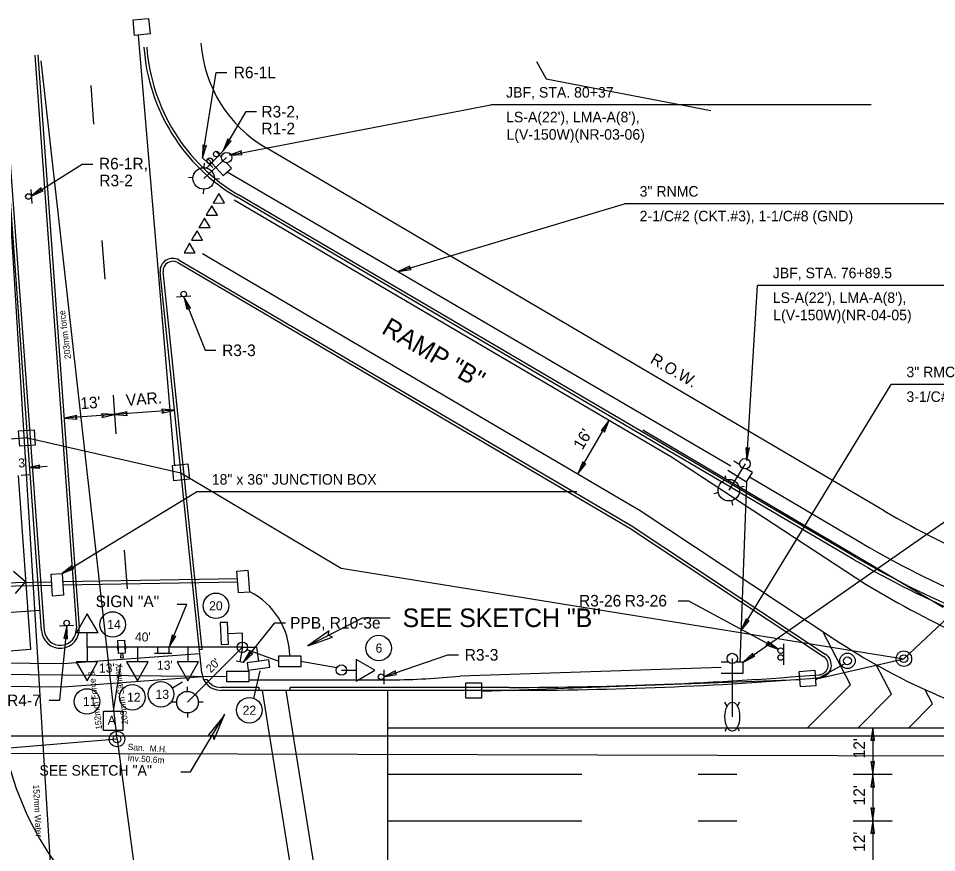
# Model space of a CAD drawing. Extents: x 488740 to 507913, y 466518 to 497949.
# Drawn here: x 503498.8 to 503735.9, y 496091.2 to 496306.6 of the extents above; entities that cross this region are included whole.
import ezdxf

# ---------------------------------------------------------------- set-up
doc = ezdxf.new("R2010")
doc.units = 0
for name, color, linetype in [('1', 7, 'Continuous'), ('11', 7, 'Continuous'), ('23', 7, 'Continuous'), ('31', 7, 'Continuous'), ('36', 7, 'Continuous'), ('38', 7, 'Continuous'), ('41', 7, 'Continuous'), ('5', 7, 'Continuous'), ('7', 7, 'Continuous'), ('9', 7, 'Continuous')]:
    doc.layers.add(name, color=color, linetype=linetype)

msp = doc.modelspace()

# ---------------------------------------------------------------- linework, layer by layer
at = {"layer": '1'}
for p, q in [((503504.8, 496148.54), (503494.11, 496296.42)), ((503505.55, 496148.6), (503494.86, 496296.48)), ((503503.13, 496297.07), (503513.82, 496149.2)), ((503503.88, 496297.13), (503514.57, 496149.25)), ((503722.34, 496179.43), (503562.78, 496273.13)), ((503714.59, 496166.85), (503555.3, 496260.39)), ((503714.97, 496167.5), (503555.68, 496261.04)), ((503539.97, 496243.53), (503656.64, 496175.01)), ((503540.35, 496244.17), (503657.04, 496175.65)), ((503546.19, 496137.67), (503535.44, 496241.12)), ((503546.32, 496143.64), (503536.18, 496241.2)), ((503656.64, 496175.01), (503706.67, 496141.85)), ((503657.04, 496175.65), (503707.08, 496142.47)), ((503546.32, 496143.64), (503545.57, 496143.56)), ((503547.52, 496135.89), (503546.71, 496135.8)), ((503560.96, 496133.88), (503551.07, 496133.88)), ((503560.96, 496133.08), (503560.96, 496133.88)), ((503568.97, 496133.08), (503568.97, 496133.88)), ((503625.63, 496133.88), (503568.97, 496133.88)), ((503625.63, 496133.12), (503551.07, 496133.12))]:
    msp.add_line(p, q, dxfattribs=at)
for points in [[(503528.44, 496306.17), (503532.42, 496306.58), (503532.84, 496302.6), (503528.86, 496302.19)], [(503498.92, 496200.1), (503502.92, 496200.39), (503503.2, 496196.4), (503499.21, 496196.11)], [(503538.6, 496191.16), (503542.58, 496191.57), (503542.99, 496187.59), (503539.01, 496187.18)], [(503700.73, 496134.02), (503700.43, 496138.01), (503704.42, 496138.32), (503704.73, 496134.32)], [(503614.38, 496131.07), (503614.38, 496135.07), (503618.38, 496135.07), (503618.38, 496131.07)]]:
    msp.add_lwpolyline(points, close=True, dxfattribs=at)
for centre, radius in [((503727.42, 496141.28), 2), ((503712.86, 496140.74), 2), ((503712.86, 496140.74), 0.999), ((503727.42, 496141.28), 0.999)]:
    msp.add_circle(centre, radius, dxfattribs=at)
for centre, radius, start, end in [((503580.11, 496302.64), 34.22, 184.1335, 239.5771), ((503580.11, 496302.64), 48.99, 184.1335, 239.577), ((503580.11, 496302.64), 48.24, 184.1335, 239.577), ((503538.69, 496241.36), 3.27, 59.577, 184.1335), ((503538.69, 496241.36), 2.51, 59.577, 184.1335), ((503838.63, 496378.08), 230.18, 239.6562, 254.7212), ((503838.63, 496378.08), 244.21, 239.577, 254.7212), ((503838.63, 496378.08), 244.96, 239.577, 254.7212), ((503509.68, 496148.9), 4.9, 184.1335, 4.1335), ((503509.68, 496148.9), 4.15, 184.1335, 4.1335), ((503705.4, 496139.68), 2.51, 274.6874, 59.577), ((503705.43, 496139.66), 3.27, 274.6874, 59.577), ((503551.07, 496138.02), 4.9, 184.1335, 270), ((503625.63, 497112.95), 979.07, 270.00005, 274.68735), ((503625.63, 497112.95), 979.83, 270.00005, 274.68735), ((503551.07, 496138.02), 4.15, 210.9627, 270)]:
    msp.add_arc(centre, radius, start, end, dxfattribs=at)
at = {"layer": '11'}
for p, q in [((503553.31, 496271.28), (503620.8, 496284.24)), ((503718.98, 496284.24), (503620.8, 496284.24)), ((503596.89, 496241.24), (503655.28, 496258.68)), ((503753.47, 496258.68), (503655.28, 496258.68)), ((503686.92, 496192.41), (503689.65, 496237.62)), ((503787.84, 496237.62), (503689.65, 496237.62)), ((503685.37, 496148.52), (503724.14, 496212.06)), ((503822.32, 496212.06), (503724.14, 496212.06)), ((503685.96, 496140.4), (503758.51, 496190.99)), ((503543.3, 496112.11), (503552.14, 496126.95)), ((503540.82, 496112.11), (503543.3, 496112.11))]:
    msp.add_line(p, q, dxfattribs=at)
for points in [[(503553.31, 496271.28), (503556.65, 496271.44), (503556.21, 496271.84), (503556.47, 496272.37)], [(503596.89, 496241.24), (503600.2, 496241.73), (503599.72, 496242.08), (503599.93, 496242.64)], [(503686.92, 496192.41), (503687.59, 496195.69), (503687.1, 496195.36), (503686.65, 496195.74)], [(503685.37, 496148.52), (503687.49, 496151.1), (503686.91, 496151.04), (503686.69, 496151.59)], [(503685.96, 496140.4), (503688.94, 496141.91), (503688.38, 496142.09), (503688.4, 496142.68)], [(503551.97, 496126.6), (503547.77, 496121.4), (503548.95, 496121.53), (503549.4, 496120.43)]]:
    msp.add_lwpolyline(points, close=True, dxfattribs=at)
at = {"layer": '23'}
for p, q in [((503539.25, 496191.18), (503529.88, 496302.17)), ((503524.39, 495809.94), (503494.31, 496296.44)), ((503524.31, 496120.55), (503504.75, 496295.61)), ((503632.55, 496295.45), (503635.11, 496291.01)), ((503635.11, 496291.01), (503677.55, 496282.8)), ((503660.06, 496200.34), (503737.56, 496154.62)), ((503501.21, 496198.3), (503462.11, 496195.47)), ((503501.21, 496198.3), (503540.8, 496189.26)), ((503540.76, 496189.27), (503582.14, 496164.63)), ((503582.14, 496164.63), (503727.42, 496141.28)), ((503727.42, 496141.28), (503738.89, 496152.04)), ((503704.86, 496136.06), (503727.42, 496141.28)), ((503704.62, 496135.86), (503712.36, 496140.14)), ((503618.76, 496132.9), (503700.59, 496135.96)), ((503524.31, 496120.55), (503402.79, 496110.21)), ((503524.31, 496120.55), (503546.14, 495959.54)), ((503398.08, 496117.2), (503762.28, 496116.11))]:
    msp.add_line(p, q, dxfattribs=at)
for radius in [2, 0.999]:
    msp.add_circle((503524.31, 496120.55), radius, dxfattribs=at)
at = {"layer": '31'}
for p, q in [((503501.75, 496190.65), (503506.31, 496190.98)), ((503498.76, 496188.54), (503502.01, 496143.63)), ((503501.53, 496188.74), (503499.55, 496188.59)), ((503537.77, 496144.23), (503542.32, 496155.34)), ((503539.84, 496155.34), (503542.32, 496155.34)), ((503516.59, 496144.23), (503516.59, 496148.01)), ((503556.66, 496147.89), (503553, 496147.72)), ((503556.66, 496144.23), (503556.66, 496147.89)), ((503502.01, 496143.63), (503484.03, 496142.33)), ((503556.66, 496144.23), (503516.59, 496144.23)), ((503516.59, 496144.23), (503516.59, 496140.45)), ((503529.61, 496144.23), (503529.61, 496140.45)), ((503534.82, 496142.69), (503534.82, 496144.23)), ((503537.77, 496142.69), (503537.77, 496144.23)), ((503542.63, 496144.23), (503542.63, 496140.45)), ((503556.66, 496144.23), (503555.98, 496140.51)), ((503556.66, 496144.23), (503560.32, 496144.23)), ((503560.32, 496144.23), (503560.83, 496140.6)), ((503533.99, 496142.69), (503538.48, 496142.69)), ((503556.91, 496140.34), (503555.05, 496140.68)), ((503559.63, 496131.04), (503561.24, 496138.12)), ((503582.22, 496138.35), (503586, 496138.35)), ((503538.59, 496133.77), (503541.23, 496135.34))]:
    msp.add_line(p, q, dxfattribs=at)
for points in [[(503501.75, 496190.65), (503504.42, 496190.46), (503504.11, 496190.82), (503504.37, 496191.22)], [(503516.59, 496152.85), (503513.87, 496148.01), (503516.59, 496148.01), (503519.43, 496148.01)], [(503550.97, 496150.59), (503551.23, 496144.92), (503553.12, 496145.01), (503552.86, 496150.67)], [(503537.77, 496144.23), (503539.46, 496147.11), (503538.89, 496146.96), (503538.58, 496147.47)], [(503558.18, 496138.32), (503563.79, 496139.12), (503563.52, 496140.99), (503557.91, 496140.19)], [(503590.84, 496138.35), (503586, 496141.07), (503586, 496138.35), (503586, 496135.52)], [(503516.59, 496135.61), (503519.31, 496140.45), (503516.59, 496140.45), (503513.76, 496140.45)], [(503529.61, 496135.61), (503532.33, 496140.45), (503529.61, 496140.45), (503526.78, 496140.45)], [(503542.63, 496135.61), (503545.35, 496140.45), (503542.63, 496140.45), (503539.8, 496140.45)]]:
    msp.add_lwpolyline(points, close=True, dxfattribs=at)
for centre, radius in [((503552.61, 496270.66), 1.34), ((503686.41, 496191.63), 1.34), ((503549.84, 496154.94), 3.29), ((503523.19, 496150.12), 3.29), ((503591.86, 496144.03), 3.29), ((503556.66, 496144.23), 1.34), ((503683.12, 496141.35), 1.34), ((503582.22, 496138.35), 1.34), ((503528.27, 496131.33), 3.29), ((503535.66, 496132.1), 3.29), ((503516.55, 496130.25), 3.29), ((503558.46, 496127.97), 3.29)]:
    msp.add_circle(centre, radius, dxfattribs=at)
at = {"layer": '36'}
for p, q in [((503517.51, 496289.22), (503518.23, 496279.23)), ((503554.52, 496259.71), (503667.46, 496193.39)), ((503520.4, 496249.26), (503521.12, 496239.27)), ((503546.4, 496245.89), (503659.34, 496179.57)), ((503523.28, 496209.3), (503524.01, 496199.31)), ((503667.46, 496193.39), (503717.71, 496160.47)), ((503659.34, 496179.57), (503709.59, 496146.26)), ((503526.17, 496169.34), (503526.89, 496159.35)), ((503497.59, 496163.89), (503500.67, 496161.22)), ((503500.67, 496161.22), (503498, 496158.13)), ((503457, 496150.43), (503504.41, 496153.85)), ((503713.65, 496134.55), (503706.49, 496148.31)), ((503510.32, 496140.01), (503545.67, 496142.65)), ((503447.68, 496140.72), (503510.32, 496140.01)), ((503724.24, 496132.09), (503720.29, 496139.69)), ((503510.51, 496134), (503546.36, 496136.68)), ((503435.97, 496134.84), (503510.51, 496134)), ((503702.57, 496123.48), (503713.65, 496134.55)), ((503581.59, 496010.27), (503561.88, 496133.12)), ((503587.77, 496009.65), (503567.97, 496133.08)), ((503594.18, 496071.42), (503594.17, 496133.12)), ((503715.63, 496123.48), (503724.24, 496132.09)), ((503734.84, 496129.63), (503732.93, 496133.29)), ((503728.69, 496123.48), (503734.84, 496129.63)), ((503594.17, 496123.48), (503761.31, 496123.48)), ((503594.17, 496111.46), (503644.25, 496111.46)), ((503674.3, 496111.46), (503684.32, 496111.46)), ((503714.37, 496111.46), (503724.38, 496111.46)), ((503594.17, 496099.44), (503644.25, 496099.44)), ((503674.3, 496099.44), (503684.32, 496099.44)), ((503714.37, 496099.44), (503724.38, 496099.44))]:
    msp.add_line(p, q, dxfattribs=at)
for points in [[(503552.08, 496258.98), (503550.6, 496261.35), (503549.88, 496260.13), (503549.16, 496258.91)], [(503550.22, 496255.82), (503548.74, 496258.2), (503548.02, 496256.97), (503547.31, 496255.75)], [(503548.31, 496252.56), (503546.89, 496255.04), (503546.17, 496253.82), (503545.45, 496252.59)], [(503546.4, 496249.3), (503544.97, 496251.78), (503544.26, 496250.56), (503543.54, 496249.34)], [(503544.48, 496246.04), (503543.06, 496248.52), (503542.34, 496247.3), (503541.62, 496246.08)]]:
    msp.add_lwpolyline(points, close=True, dxfattribs=at)
for centre, radius, start, end in [((503851.62, 496381.27), 258.23, 238.7636, 252.127), ((503800.29, 496282.06), 163.3, 236.2647, 256.1902), ((503575.88, 496135.92), 82.51, 189.6092, 269.9061)]:
    msp.add_arc(centre, radius, start, end, dxfattribs=at)
at = {"layer": '38'}
for p, q in [((503539.15, 496205.42), (503523.65, 496204.3)), ((503523.65, 496204.3), (503510.66, 496203.37)), ((503643.26, 496189.01), (503651.37, 496202.83)), ((503719.37, 496123.48), (503719.37, 496111.46)), ((503719.37, 496111.46), (503719.37, 496099.44)), ((503719.37, 496099.44), (503719.37, 496087.42))]:
    msp.add_line(p, q, dxfattribs=at)
for points in [[(503523.65, 496204.3), (503526.98, 496204.07), (503526.59, 496204.52), (503526.91, 496205.01)], [(503539.15, 496205.42), (503535.81, 496205.66), (503536.2, 496205.21), (503535.88, 496204.71)], [(503510.66, 496203.37), (503513.99, 496203.13), (503513.6, 496203.58), (503513.92, 496204.08)], [(503523.65, 496204.3), (503520.31, 496204.54), (503520.7, 496204.09), (503520.38, 496203.59)], [(503651.37, 496202.83), (503649.29, 496200.22), (503649.88, 496200.29), (503650.11, 496199.74)], [(503643.26, 496189.01), (503645.34, 496191.63), (503644.75, 496191.56), (503644.52, 496192.11)], [(503719.37, 496123.48), (503718.9, 496120.17), (503719.37, 496120.53), (503719.85, 496120.17)], [(503719.37, 496111.46), (503719.85, 496114.77), (503719.37, 496114.41), (503718.9, 496114.77)], [(503719.37, 496111.46), (503718.9, 496108.15), (503719.37, 496108.51), (503719.85, 496108.15)], [(503719.37, 496099.44), (503719.85, 496102.75), (503719.37, 496102.39), (503718.9, 496102.75)], [(503719.37, 496099.44), (503718.9, 496096.13), (503719.37, 496096.49), (503719.85, 496096.13)]]:
    msp.add_lwpolyline(points, close=True, dxfattribs=at)
at = {"layer": '41'}
for p, q in [((503546.4, 496270.6), (503549.94, 496292.63)), ((503549.94, 496292.63), (503552.65, 496292.63)), ((503551.68, 496272.36), (503557.62, 496282.51)), ((503557.62, 496282.51), (503560.33, 496282.51)), ((503551.68, 496272.36), (503549.16, 496269.71)), ((503502.16, 496260.66), (503515.33, 496268.95)), ((503515.33, 496268.95), (503518.04, 496268.95)), ((503549.06, 496268.08), (503546.4, 496270.6)), ((503550, 496270.61), (503547.48, 496267.96)), ((503502.02, 496262.43), (503502.28, 496258.77)), ((503543.35, 496234.84), (503539.69, 496234.58)), ((503541.58, 496234.7), (503547.1, 496220.9)), ((503547.1, 496220.9), (503549.81, 496220.9)), ((503669.13, 496156.25), (503671.84, 496156.25)), ((503671.84, 496156.25), (503694.95, 496143.71)), ((503556.91, 496140.34), (503565.06, 496150.57)), ((503565.06, 496150.57), (503567.77, 496150.57)), ((503513.11, 496149.84), (503509.45, 496149.7)), ((503511.34, 496149.76), (503509.48, 496130.54)), ((503696.32, 496145.13), (503696.32, 496141.47)), ((503696.33, 496143.36), (503696.33, 496139.7)), ((503593.2, 496136.62), (503609.74, 496142.29)), ((503609.74, 496142.29), (503612.45, 496142.29)), ((503593.19, 496138.39), (503593.19, 496134.73)), ((503506.77, 496130.54), (503509.48, 496130.54))]:
    msp.add_line(p, q, dxfattribs=at)
for points in [[(503546.4, 496270.6), (503547.39, 496273.79), (503546.87, 496273.52), (503546.46, 496273.94)], [(503551.68, 496272.36), (503553.76, 496274.98), (503553.17, 496274.91), (503552.94, 496275.46)], [(503502.16, 496260.66), (503505.21, 496262.02), (503504.66, 496262.23), (503504.71, 496262.82)], [(503541.58, 496234.7), (503542.37, 496231.45), (503542.68, 496231.96), (503543.25, 496231.81)], [(503511.34, 496149.76), (503510.55, 496146.51), (503511.05, 496146.82), (503511.49, 496146.42)], [(503694.95, 496143.71), (503692.27, 496145.7), (503692.35, 496145.12), (503691.82, 496144.87)], [(503556.91, 496140.34), (503559.34, 496142.63), (503558.75, 496142.65), (503558.6, 496143.22)], [(503593.2, 496136.62), (503596.48, 496137.24), (503595.99, 496137.57), (503596.17, 496138.14)]]:
    msp.add_lwpolyline(points, close=True, dxfattribs=at)
for centre in [(503549.94, 496271.56), (503548.26, 496269.82), (503548.26, 496269.82), (503501.44, 496260.61), (503541.53, 496235.42), (503511.31, 496150.48), (503695.61, 496143.36), (503695.62, 496141.59), (503592.48, 496136.62)]:
    msp.add_circle(centre, 0.721, dxfattribs=at)
at = {"layer": '5'}
for p, q in [((503551.27, 496270.72), (503550, 496272.11)), ((503547.91, 496270.19), (503551.74, 496266.02)), ((503553.83, 496267.93), (503552.55, 496269.33)), ((503551.74, 496266.02), (503553.83, 496267.93)), ((503552.77, 496266.99), (503682.77, 496191.11)), ((503685.11, 496191.32), (503683.5, 496192.32)), ((503682.01, 496189.92), (503686.82, 496186.92)), ((503688.32, 496189.33), (503686.71, 496190.33)), ((503686.82, 496186.92), (503688.32, 496189.33)), ((503686.8, 496186.93), (503685.07, 496140.4)), ((503716.95, 496170.87), (503687.55, 496188.14)), ((503458.16, 496159.43), (503507.49, 496160.27)), ((503458.46, 496160.29), (503507.42, 496161.13)), ((503510.28, 496161.18), (503555.38, 496161.95)), ((503510.34, 496160.32), (503555.47, 496161.09)), ((503524.68, 496143.52), (503524.61, 496145.01)), ((503524.68, 496143.52), (503524.61, 496145.01)), ((503526.31, 496145.1), (503526.38, 496143.6)), ((503526.31, 496145.1), (503526.38, 496143.6)), ((503557.85, 496143.62), (503566.06, 496140.66)), ((503523.36, 496127.74), (503525.31, 496139.94)), ((503571.72, 496140.66), (503581.04, 496138.98)), ((503680.29, 496138.99), (503612.88, 496136.77)), ((503682.18, 496140.4), (503680.29, 496140.4)), ((503685.96, 496140.4), (503684.07, 496140.4)), ((503685.96, 496137.57), (503685.96, 496140.4)), ((503432.95, 496137.91), (503552.64, 496136.71)), ((503680.29, 496137.57), (503685.96, 496137.57)), ((503558.31, 496135.82), (503595.13, 496135.82)), ((503520.84, 496122.78), (503520.84, 496127.74)), ((503520.84, 496127.74), (503525.8, 496127.74)), ((503525.8, 496127.74), (503525.8, 496122.78)), ((503525.8, 496122.78), (503520.84, 496122.78)), ((503438.74, 496121.4), (503760.91, 496121.4))]:
    msp.add_line(p, q, dxfattribs=at)
for points in [[(503510.11, 496163.3), (503510.52, 496157.65), (503507.69, 496157.44), (503507.28, 496163.1), (503510.11, 496163.3)], [(503558.1, 496164.12), (503558.5, 496158.47), (503555.68, 496158.26), (503555.27, 496163.92), (503558.1, 496164.12)], [(503571.74, 496139.23), (503566.07, 496139.23), (503566.07, 496142.06), (503571.74, 496142.06), (503571.74, 496139.23)], [(503558.33, 496135.28), (503552.66, 496135.28), (503552.66, 496138.11), (503558.33, 496138.11), (503558.33, 496135.28)]]:
    msp.add_lwpolyline(points, dxfattribs=at)
for points in [[(503524.72, 496142.59), (503524.56, 496146), (503526.26, 496146.08), (503526.42, 496142.68)], [(503524.72, 496142.59), (503524.56, 496146), (503526.26, 496146.08), (503526.42, 496142.68)], [(503525.29, 496142.62), (503525.19, 496141.55), (503526.02, 496141.6), (503525.82, 496142.65)], [(503525.29, 496142.62), (503525.19, 496141.55), (503526.02, 496141.6), (503525.82, 496142.65)]]:
    msp.add_lwpolyline(points, close=True, dxfattribs=at)
for centre, radius, start, end in [((503838.63, 496378.08), 240.29, 239.5771, 254.7211), ((503550.12, 496141.8), 18.77, 0.8604, 63.1431), ((503525.49, 496144.31), 1.13, 141.381, 224.1988), ((503525.49, 496144.31), 1.13, 141.381, 224.1988), ((503525.49, 496144.31), 1.13, 321.3807, 44.2003), ((503525.49, 496144.31), 1.13, 321.3807, 44.2003), ((503592.07, 496358.28), 222.49, 270.7879, 275.3669)]:
    msp.add_arc(centre, radius, start, end, dxfattribs=at)
at = {"layer": '7'}
for p, q in [((503552.61, 496270.66), (503546.69, 496265.26)), ((503546.78, 496269.18), (503546.73, 496268.02)), ((503543.91, 496265.41), (503542.72, 496265.47)), ((503546.69, 496265.26), (503546.69, 496265.26)), ((503550.73, 496265.1), (503549.47, 496265.16)), ((503546.6, 496262.48), (503546.55, 496261.28)), ((503686.41, 496191.63), (503682.24, 496184.78)), ((503681.23, 496188.58), (503681.51, 496187.44)), ((503679.53, 496184.15), (503678.38, 496183.87)), ((503682.24, 496184.78), (503682.24, 496184.78)), ((503686.17, 496185.77), (503684.94, 496185.47)), ((503682.94, 496182.09), (503683.22, 496180.92)), ((503556.66, 496144.23), (503542.49, 496130.06)), ((503683.12, 496141.35), (503683.12, 496126.32)), ((503542.41, 496133.99), (503542.41, 496132.82)), ((503539.71, 496130.09), (503538.52, 496130.09)), ((503542.49, 496130.06), (503542.49, 496130.06)), ((503546.54, 496130.09), (503545.27, 496130.09)), ((503681.83, 496129.04), (503681.23, 496130.1)), ((503685.01, 496130.1), (503684.42, 496128.92)), ((503542.53, 496127.28), (503542.53, 496126.08)), ((503683.12, 496126.32), (503683.12, 496126.32)), ((503681.83, 496123.61), (503681.23, 496122.54)), ((503685.01, 496122.54), (503684.42, 496123.73))]:
    msp.add_line(p, q, dxfattribs=at)
for centre in [(503546.69, 496265.26), (503682.24, 496184.78), (503542.49, 496130.06)]:
    msp.add_circle(centre, 2.78, dxfattribs=at)
msp.add_ellipse((503683.12, 496126.32), major_axis=(0, 3.76), ratio=0.504, dxfattribs=at)
at = {"layer": '9'}
for p, q in [((503510.13, 496163.26), (503544.84, 496184.32)), ((503643.02, 496184.32), (503544.84, 496184.32)), ((503642.49, 496184.32), (503544.84, 496184.32)), ((503573.57, 496144.65), (503587.66, 496151.85)), ((503587.66, 496151.85), (503594.84, 496151.85))]:
    msp.add_line(p, q, dxfattribs=at)
for points in [[(503510.13, 496163.26), (503513.2, 496164.57), (503512.65, 496164.79), (503512.71, 496165.38)], [(503573.57, 496144.65), (503579.89, 496146.82), (503578.83, 496147.34), (503579.03, 496148.5)]]:
    msp.add_lwpolyline(points, close=True, dxfattribs=at)

# ---------------------------------------------------------------- texts
at = {"layer": '1'}
for s, height, p in [('RAMP "B"', 4.796, (503592.31, 496225.46)), ('R.O.W.', 2.993, (503661.7, 496217.77))]:
    msp.add_text(s, height=height, rotation=329.577, dxfattribs=at).set_placement(p)
at = {"layer": '11'}
for s, p in [('JBF, STA. 80+37                    ', (503624.73, 496286.13)), ("LS-A(22'), LMA-A(8'),                          ", (503624.73, 496279.75)), ('L(V-150W)(NR-03-06)                            ', (503624.84, 496275.26)), ('3" RNMC                            ', (503659.21, 496260.57)), ('2-1/C#2 (CKT.#3), 1-1/C#8 (GND)                ', (503659.21, 496254.2)), ('JBF, STA. 76+89.5                  ', (503693.58, 496239.5)), ("LS-A(22'), LMA-A(8'),                          ", (503693.58, 496233.13)), ('L(V-150W)(NR-04-05)                           ', (503693.7, 496228.64)), ('3" RMC                             ', (503728.07, 496213.95)), ('3-1/C#2 (CKTS.#3,4), 1-1/C#8 (GND)             ', (503728.07, 496207.57)), ('SEE SKETCH "A"', (503504.29, 496111.09))]:
    msp.add_text(s, height=2.7163, dxfattribs=at).set_placement(p)
at = {"layer": '23'}
for s, height, rotation, p in [('203mm force', 1.6204, 97.198, (503512.44, 496218.76)), ('203mm Sanitary', 1.6204, 97.6922, (503527.21, 496124.39)), ('152mm Force & ', 1.6204, 97.6922, (503520.49, 496123.08)), ('San.  M.H.', 1.62, 356.0653, (503527.04, 496117.75)), ('Inv.50.6m', 1.62, 356.0653, (503527, 496114.89)), ('152mm Water', 1.6205, 273.0647, (503502.63, 496108.74))]:
    msp.add_text(s, height=height, rotation=rotation, dxfattribs=at).set_placement(p)
at = {"layer": '31'}
msp.add_text("3'", height=2.344, rotation=4.1334, dxfattribs=at).set_placement((503498.91, 496190.6))
for s, height, p in [('SIGN "A"', 2.993, (503518.79, 496154.6)), ('20', 2.344, (503548.09, 496153.77)), ('14', 2.344, (503521.79, 496148.95)), ("40'", 2.344, (503528.94, 496145.73)), ('6', 2.34, (503591.04, 496142.85)), ("13'", 2.344, (503519.64, 496137.72)), ("13'", 2.344, (503534.62, 496138.42)), ('11', 2.344, (503515.51, 496129.07)), ('12', 2.344, (503526.9, 496130.16)), ('13', 2.344, (503534.26, 496130.92)), ('22', 2.344, (503556.73, 496126.8))]:
    msp.add_text(s, height=height, dxfattribs=at).set_placement(p)
at = {"layer": '38'}
for s, rotation, p in [('VAR.', 4.1334, (503526.7, 496206.54)), ("13'", 4.1333, (503514.95, 496205.68)), ("16'", 59.5768, (503644.44, 496194.98)), ("12'", 90, (503717.39, 496115.56)), ("12'", 90, (503717.4, 496103.42)), ("12'", 90, (503717.4, 496091.42))]:
    msp.add_text(s, height=2.993, rotation=rotation, dxfattribs=at).set_placement(p)
at = {"layer": '41'}
for s, height, p in [('R6-1L', 2.993, (503554.42, 496291.13)), ('R3-2,', 2.993, (503561.57, 496281)), ('R1-2', 2.993, (503561.58, 496276.66)), ('R6-1R,', 2.993, (503519.63, 496267.59)), ('R3-2', 2.993, (503519.73, 496263.23)), ('R3-3', 2.993, (503551.44, 496219.4)), ('R3-26', 2.993, (503643.56, 496154.76)), ('R3-26', 2.993, (503655.36, 496154.76)), ('PPB, R10-3e', 2.9928, (503568.99, 496149.05)), ('R3-3', 2.993, (503614.07, 496140.79)), ('R4-7', 2.993, (503495.94, 496129.04))]:
    msp.add_text(s, height=height, dxfattribs=at).set_placement(p)
at = {"layer": '5'}
msp.add_text('A', height=2.34, dxfattribs=at).set_placement((503521.88, 496124.23))
at = {"layer": '7'}
msp.add_text("20'", height=2.109, rotation=45.0006, dxfattribs=at).set_placement((503548.51, 496137.53))
at = {"layer": '9'}
for s, height, p in [('18" x 36" JUNCTION BOX                  ', 2.7163, (503548.77, 496186.21)), ('SEE SKETCH "B"', 4.7957, (503598.02, 496149.45))]:
    msp.add_text(s, height=height, dxfattribs=at).set_placement(p)

doc.saveas('drawing.dxf')
